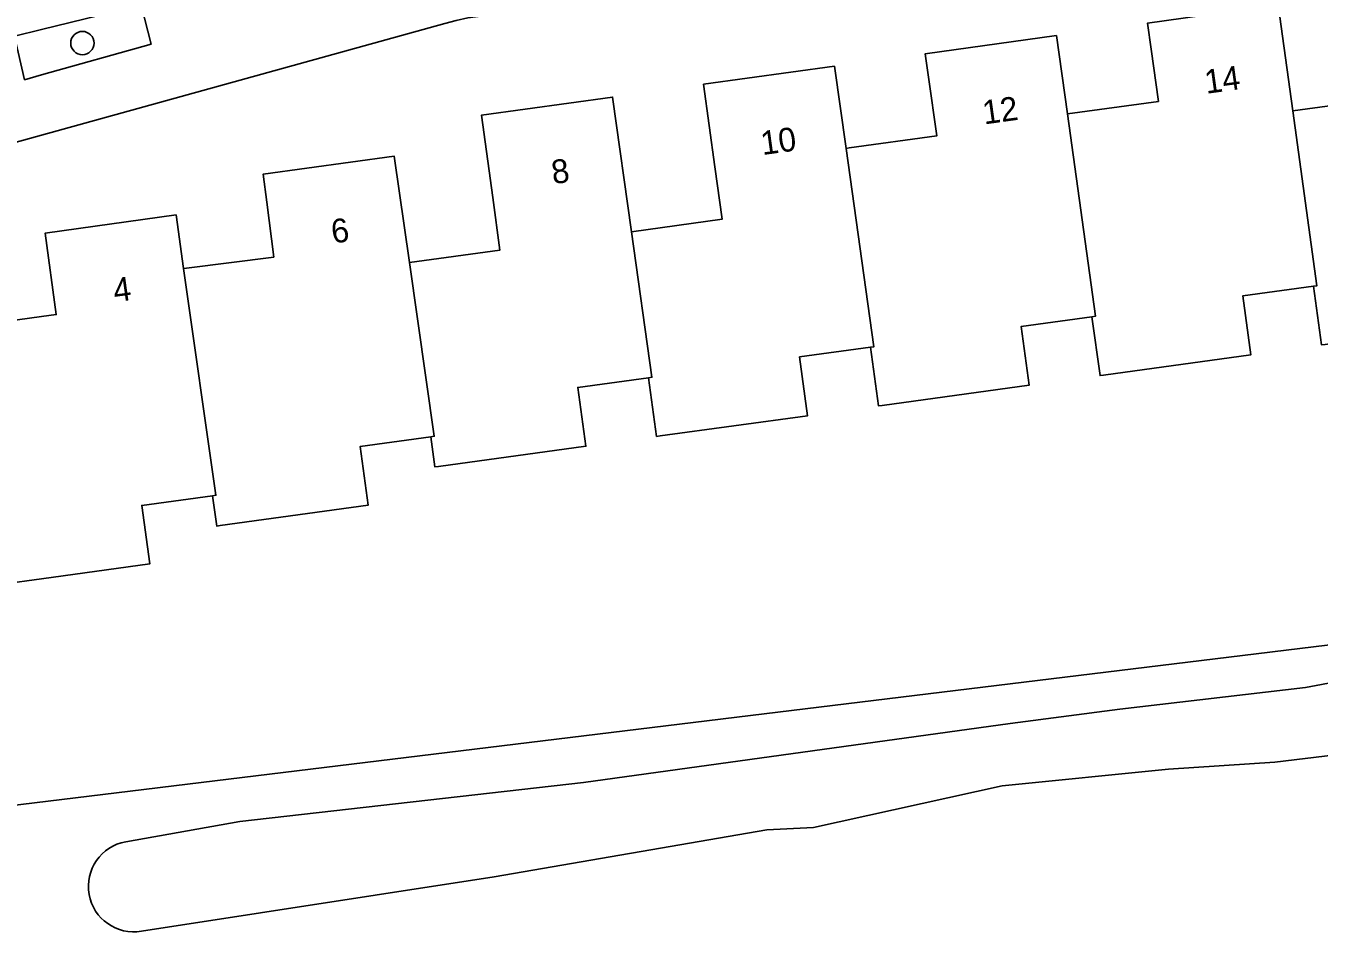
# Model space of a CAD drawing. Extents: x 163427 to 164190, y 380331 to 381641.
# Drawn here: x 163499.3 to 163553.6, y 380854.6 to 380893.3 of the extents above; entities that cross this region are included whole.
import ezdxf

# ---------------------------------------------------------------- set-up
doc = ezdxf.new("R2010")
doc.units = 0
for name, color, linetype in [('IMGEO_Boom', 7, 'Continuous'), ('IMGEO_Gemengd_bos', 7, 'Continuous'), ('IMGEO_Pand', 7, 'Continuous'), ('IMGEO_Pand_nummerreeks', 7, 'Continuous'), ('IMGEO_Voetpad_open', 7, 'Continuous'), ('IMGEO_Waterloop', 7, 'Continuous')]:
    doc.layers.add(name, color=color, linetype=linetype)

msp = doc.modelspace()

# ---------------------------------------------------------------- linework, layer by layer
at = {"layer": 'IMGEO_Boom'}
msp.add_circle((163501.716, 380892.547), 0.489, dxfattribs=at)
at = {"layer": 'IMGEO_Gemengd_bos'}
msp.add_lwpolyline([(163493.384, 380859.911), (163586.726, 380871.286)], dxfattribs=at)
at = {"layer": 'IMGEO_Pand'}
for points in [[(163552.496, 380889.7), (163556.301, 380890.225), (163555.997, 380892.424), (163555.687, 380894.67), (163561.178, 380895.428), (163561.962, 380889.797)], [(163543.037, 380889.576), (163546.857, 380890.102), (163546.555, 380892.298), (163546.405, 380893.388), (163551.882, 380894.145), (163552.496, 380889.7)], [(163533.751, 380888.128), (163533.888, 380888.147), (163537.555, 380888.653), (163537.216, 380891.111), (163537.079, 380892.102), (163542.581, 380892.861), (163543.037, 380889.576)], [(163524.753, 380884.634), (163528.555, 380885.16), (163528.251, 380887.359), (163527.773, 380890.818), (163533.266, 380891.576), (163533.751, 380888.128)], [(163515.437, 380883.347), (163519.229, 380883.862), (163518.928, 380886.074), (163518.459, 380889.523), (163523.959, 380890.281), (163524.753, 380884.634)], [(163544.07, 380881.072), (163544.216, 380881.092), (163543.037, 380889.576)], [(163552.496, 380889.7), (163553.509, 380882.371), (163553.362, 380882.351)], [(163533.751, 380888.128), (163534.921, 380879.813), (163534.779, 380879.793)], [(163505.964, 380883.097), (163506.078, 380883.111), (163509.745, 380883.574), (163509.456, 380885.868), (163509.306, 380887.053), (163514.798, 380887.798), (163515.437, 380883.347)], [(163496.837, 380880.648), (163496.972, 380880.666), (163500, 380881.076), (163500.619, 380881.16), (163500.156, 380884.58), (163505.645, 380885.34), (163505.964, 380883.097)], [(163525.468, 380878.511), (163525.611, 380878.531), (163524.753, 380884.634)], [(163562.67, 380883.653), (163559.701, 380883.244), (163560.043, 380880.76), (163553.85, 380879.908), (163553.701, 380879.887), (163553.362, 380882.351)], [(163507.175, 380873.563), (163507.318, 380873.583), (163505.964, 380883.097)], [(163515.437, 380883.347), (163516.474, 380876.054), (163516.332, 380876.034)], [(163553.362, 380882.351), (163550.393, 380881.942), (163550.734, 380879.469), (163544.56, 380878.619), (163544.411, 380878.598), (163544.07, 380881.072)], [(163544.07, 380881.072), (163541.102, 380880.663), (163541.441, 380878.2), (163535.267, 380877.35), (163535.118, 380877.329), (163534.779, 380879.793)], [(163534.779, 380879.793), (163531.801, 380879.383), (163532.14, 380876.919), (163525.957, 380876.069), (163525.807, 380876.048), (163525.468, 380878.511)], [(163525.468, 380878.511), (163522.5, 380878.103), (163522.839, 380875.639), (163516.655, 380874.788), (163516.506, 380874.767), (163516.332, 380876.034)], [(163516.332, 380876.034), (163513.364, 380875.625), (163513.703, 380873.161), (163507.499, 380872.308), (163507.35, 380872.287), (163507.175, 380873.563)], [(163507.175, 380873.563), (163504.206, 380873.155), (163504.544, 380870.701), (163500, 380870.075), (163498.37, 380869.851), (163498.221, 380869.83), (163498.047, 380871.097)]]:
    msp.add_lwpolyline(points, dxfattribs=at)
at = {"layer": 'IMGEO_Voetpad_open'}
for points in [[(163591.127, 380903.206), (163517.891, 380893.601), (163517.396, 380893.496), (163516.914, 380893.369), (163500, 380888.682), (163485.003, 380884.527)], [(163504.606, 380892.497), (163500, 380891.21), (163499.291, 380891.012), (163498.862, 380892.835), (163500, 380893.113), (163504.18, 380894.134), (163504.606, 380892.497)]]:
    msp.add_lwpolyline(points, dxfattribs=at)
at = {"layer": 'IMGEO_Waterloop'}
for points in [[(163609.418, 380854.587), (163602.738, 380860.396), (163600.091, 380863.489), (163596.479, 380866.45), (163593.799, 380868.531), (163590.402, 380869.544), (163588.868, 380869.866), (163587.1, 380869.822), (163580.175, 380869.293), (163576.386, 380868.687), (163569.478, 380868.07), (163559.351, 380866.7), (163553.023, 380865.515), (163545.236, 380864.606), (163540.638, 380864.003), (163522.737, 380861.53), (163508.323, 380859.904), (163503.533, 380859.052)], [(163504.2, 380855.294), (163518.987, 380857.584), (163530.431, 380859.553), (163532.384, 380859.642), (163540.304, 380861.39), (163547.28, 380862.097), (163551.74, 380862.387), (163557.177, 380863.045)]]:
    msp.add_lwpolyline(points, dxfattribs=at)
msp.add_arc((163503.875, 380857.175), 1.908, 100.3274, 279.8016, dxfattribs=at)

# ---------------------------------------------------------------- texts
at = {"layer": 'IMGEO_Pand_nummerreeks'}
for s, rotation, p in [('14', 7.8667, (163548.864, 380890.417)), ('12', 7.8495, (163539.547, 380889.132)), ('10', 7.8553, (163530.243, 380887.847)), ('8', 7.8495, (163521.463, 380886.627)), ('6', 7.7177, (163512.221, 380884.138)), ('4', 7.8839, (163503.077, 380881.673))]:
    msp.add_text(s, height=1, rotation=rotation, dxfattribs=at).set_placement(p)

doc.saveas('drawing.dxf')
